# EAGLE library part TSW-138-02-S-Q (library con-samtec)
THROUGH-HOLE .025" SQ POST HEADER Source: Samtec TSW.pdf
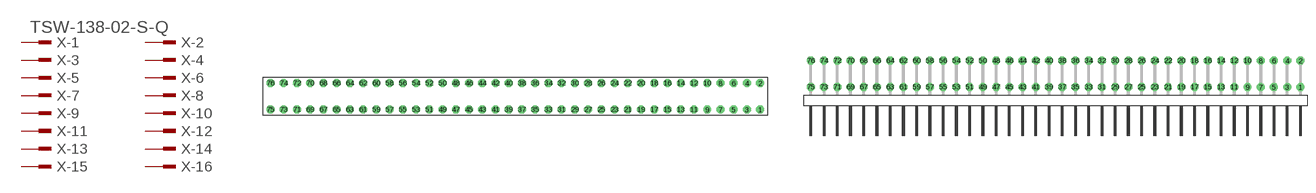
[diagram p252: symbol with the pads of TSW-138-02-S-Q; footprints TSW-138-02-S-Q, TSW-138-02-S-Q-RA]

Designator prefix X; gates -1=MPINV -2=MPIN -3=MPIN -4=MPIN -5=MPIN -6=MPIN -7=MPIN -8=MPIN -9=MPIN -10=MPIN -11=MPIN -12=MPIN -13=MPIN -14=MPIN -15=MPIN -16=MPIN -17=MPIN -18=MPIN -19=MPIN -20=MPIN -21=MPIN -22=MPIN -23=MPIN -24=MPIN -25=MPIN -26=MPIN -27=MPIN -28=MPIN -29=MPIN -30=MPIN -31=MPIN -32=MPIN -33=MPIN -34=MPIN -35=MPIN -36=MPIN -37=MPIN -38=MPIN -39=MPIN -40=MPIN -41=MPIN -42=MPIN -43=MPIN -44=MPIN -45=MPIN -46=MPIN -47=MPIN -48=MPIN -49=MPIN -50=MPIN -51=MPIN -52=MPIN -53=MPIN -54=MPIN -55=MPIN -56=MPIN -57=MPIN -58=MPIN -59=MPIN -60=MPIN -61=MPIN -62=MPIN -63=MPIN -64=MPIN -65=MPIN -66=MPIN -67=MPIN -68=MPIN -69=MPIN -70=MPIN -71=MPIN -72=MPIN -73=MPIN -74=MPIN -75=MPIN -76=MPIN

## TSW-138-02-S-Q (OC_FARNELL: unknown; OC_NEWARK: unknown)  [TSW-138-02-S-Q]
1  -1:1  pas
2  -2:1  pas
3  -3:1  pas
4  -4:1  pas
5  -5:1  pas
6  -6:1  pas
7  -7:1  pas
8  -8:1  pas
9  -9:1  pas
10  -10:1  pas
11  -11:1  pas
12  -12:1  pas
13  -13:1  pas
14  -14:1  pas
15  -15:1  pas
16  -16:1  pas
17  -17:1  pas
18  -18:1  pas
19  -19:1  pas
20  -20:1  pas
21  -21:1  pas
22  -22:1  pas
23  -23:1  pas
24  -24:1  pas
25  -25:1  pas
26  -26:1  pas
27  -27:1  pas
28  -28:1  pas
29  -29:1  pas
30  -30:1  pas
31  -31:1  pas
32  -32:1  pas
33  -33:1  pas
34  -34:1  pas
35  -35:1  pas
36  -36:1  pas
37  -37:1  pas
38  -38:1  pas
39  -39:1  pas
40  -40:1  pas
41  -41:1  pas
42  -42:1  pas
43  -43:1  pas
44  -44:1  pas
45  -45:1  pas
46  -46:1  pas
47  -47:1  pas
48  -48:1  pas
49  -49:1  pas
50  -50:1  pas
51  -51:1  pas
52  -52:1  pas
53  -53:1  pas
54  -54:1  pas
55  -55:1  pas
56  -56:1  pas
57  -57:1  pas
58  -58:1  pas
59  -59:1  pas
60  -60:1  pas
61  -61:1  pas
62  -62:1  pas
63  -63:1  pas
64  -64:1  pas
65  -65:1  pas
66  -66:1  pas
67  -67:1  pas
68  -68:1  pas
69  -69:1  pas
70  -70:1  pas
71  -71:1  pas
72  -72:1  pas
73  -73:1  pas
74  -74:1  pas
75  -75:1  pas
76  -76:1  pas

## TSW-138-02-S-Q-RA (OC_FARNELL: unknown; OC_NEWARK: unknown)  [TSW-138-02-S-Q-RA]
Pads as for TSW-138-02-S-Q

## Footprint TSW-138-02-S-Q (pad centres in mm)
THROUGH-HOLE .025" SQ POST HEADER Source: Samtec TSW.pdf
drill 1 pad 1.5 octagon: 1 46.99,-2.54; 2 46.99,2.54; 3 44.45,-2.54; 4 44.45,2.54; 5 41.91,-2.54; 6 41.91,2.54; 7 39.37,-2.54; 8 39.37,2.54; 9 36.83,-2.54; 10 36.83,2.54; 11 34.29,-2.54; 12 34.29,2.54; 13 31.75,-2.54; 14 31.75,2.54; 15 29.21,-2.54; 16 29.21,2.54; 17 26.67,-2.54; 18 26.67,2.54; 19 24.13,-2.54; 20 24.13,2.54; 21 21.59,-2.54; 22 21.59,2.54; 23 19.05,-2.54; 24 19.05,2.54; 25 16.51,-2.54; 26 16.51,2.54; 27 13.97,-2.54; 28 13.97,2.54; 29 11.43,-2.54; 30 11.43,2.54; 31 8.89,-2.54; 32 8.89,2.54; 33 6.35,-2.54; 34 6.35,2.54; 35 3.81,-2.54; 36 3.81,2.54; 37 1.27,-2.54; 38 1.27,2.54; 39 -1.27,-2.54; 40 -1.27,2.54; 41 -3.81,-2.54; 42 -3.81,2.54; 43 -6.35,-2.54; 44 -6.35,2.54; 45 -8.89,-2.54; 46 -8.89,2.54; 47 -11.43,-2.54; 48 -11.43,2.54; 49 -13.97,-2.54; 50 -13.97,2.54; 51 -16.51,-2.54; 52 -16.51,2.54; 53 -19.05,-2.54; 54 -19.05,2.54; 55 -21.59,-2.54; 56 -21.59,2.54; 57 -24.13,-2.54; 58 -24.13,2.54; 59 -26.67,-2.54; 60 -26.67,2.54; 61 -29.21,-2.54; 62 -29.21,2.54; 63 -31.75,-2.54; 64 -31.75,2.54; 65 -34.29,-2.54; 66 -34.29,2.54; 67 -36.83,-2.54; 68 -36.83,2.54; 69 -39.37,-2.54; 70 -39.37,2.54; 71 -41.91,-2.54; 72 -41.91,2.54; 73 -44.45,-2.54; 74 -44.45,2.54; 75 -46.99,-2.54; 76 -46.99,2.54

## Footprint TSW-138-02-S-Q-RA (pad centres in mm)
THROUGH-HOLE .025" SQ POST HEADER Source: Samtec TSW.pdf
drill 1 pad 1.5 octagon: 1 46.99,1.524; 2 46.99,6.604; 3 44.45,1.524; 4 44.45,6.604; 5 41.91,1.524; 6 41.91,6.604; 7 39.37,1.524; 8 39.37,6.604; 9 36.83,1.524; 10 36.83,6.604; 11 34.29,1.524; 12 34.29,6.604; 13 31.75,1.524; 14 31.75,6.604; 15 29.21,1.524; 16 29.21,6.604; 17 26.67,1.524; 18 26.67,6.604; 19 24.13,1.524; 20 24.13,6.604; 21 21.59,1.524; 22 21.59,6.604; 23 19.05,1.524; 24 19.05,6.604; 25 16.51,1.524; 26 16.51,6.604; 27 13.97,1.524; 28 13.97,6.604; 29 11.43,1.524; 30 11.43,6.604; 31 8.89,1.524; 32 8.89,6.604; 33 6.35,1.524; 34 6.35,6.604; 35 3.81,1.524; 36 3.81,6.604; 37 1.27,1.524; 38 1.27,6.604; 39 -1.27,1.524; 40 -1.27,6.604; 41 -3.81,1.524; 42 -3.81,6.604; 43 -6.35,1.524; 44 -6.35,6.604; 45 -8.89,1.524; 46 -8.89,6.604; 47 -11.43,1.524; 48 -11.43,6.604; 49 -13.97,1.524; 50 -13.97,6.604; 51 -16.51,1.524; 52 -16.51,6.604; 53 -19.05,1.524; 54 -19.05,6.604; 55 -21.59,1.524; 56 -21.59,6.604; 57 -24.13,1.524; 58 -24.13,6.604; 59 -26.67,1.524; 60 -26.67,6.604; 61 -29.21,1.524; 62 -29.21,6.604; 63 -31.75,1.524; 64 -31.75,6.604; 65 -34.29,1.524; 66 -34.29,6.604; 67 -36.83,1.524; 68 -36.83,6.604; 69 -39.37,1.524; 70 -39.37,6.604; 71 -41.91,1.524; 72 -41.91,6.604; 73 -44.45,1.524; 74 -44.45,6.604; 75 -46.99,1.524; 76 -46.99,6.604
